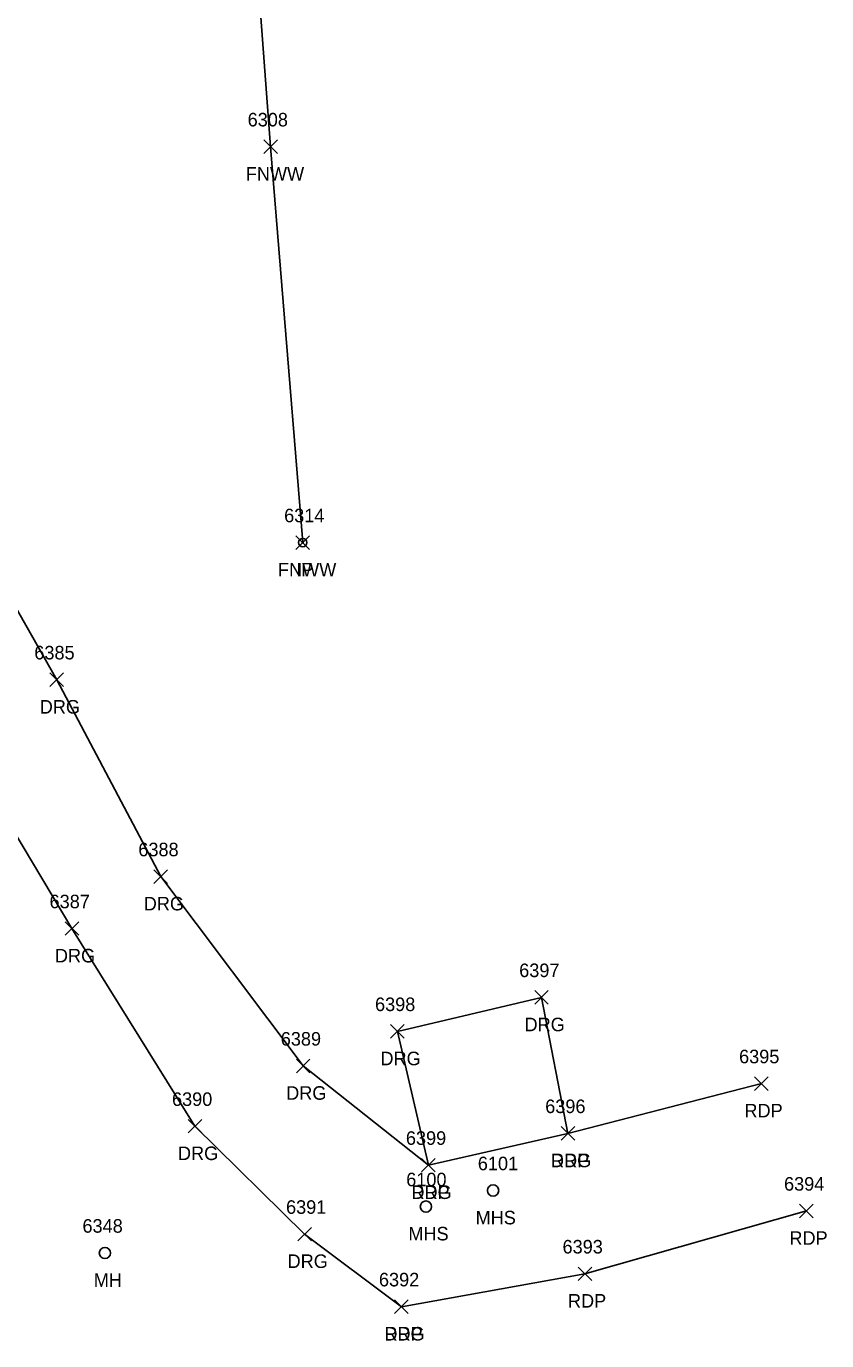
# Model space of a CAD drawing. Extents: x 1462668 to 1465147, y 550359 to 557351.
# Drawn here: x 1465029 to 1465147.2, y 551060.4 to 551254.6 of the extents above; entities that cross this region are included whole.
import ezdxf

# ---------------------------------------------------------------- set-up
doc = ezdxf.new("R2010")
doc.units = 0
for name, color, linetype in [('L_A', 7, 'Continuous'), ('L_I', 7, 'Continuous'), ('L_TIC', 7, 'Continuous'), ('LFNC', 7, 'Continuous'), ('M_A', 7, 'Continuous'), ('M_I', 7, 'Continuous'), ('MPIR', 7, 'Continuous'), ('P_A', 7, 'Continuous'), ('P_I', 7, 'Continuous'), ('P_TIC', 7, 'Continuous'), ('PET', 7, 'Continuous'), ('R_A', 7, 'Continuous'), ('R_I', 7, 'Continuous'), ('R_TIC', 7, 'Continuous'), ('RDG', 7, 'Continuous'), ('U_A', 7, 'Continuous'), ('U_I', 7, 'Continuous'), ('USMH', 7, 'Continuous'), ('UUMH', 7, 'Continuous')]:
    doc.layers.add(name, color=color, linetype=linetype)

msp = doc.modelspace()

# ---------------------------------------------------------------- linework, layer by layer
at = {"layer": 'L_TIC'}
for points in [[(1465064.12, 551235.79), (1465066.12, 551237.79)], [(1465066.12, 551235.79), (1465064.12, 551237.79)], [(1465068.86, 551177.31), (1465070.86, 551179.31)], [(1465070.86, 551177.31), (1465068.86, 551179.31)]]:
    msp.add_lwpolyline(points, dxfattribs=at)
at = {"layer": 'LFNC'}
msp.add_lwpolyline([(1465059.52, 551311.49), (1465065.12, 551236.79), (1465069.86, 551178.31)], dxfattribs=at)
at = {"layer": 'MPIR'}
for radius in [0.625, 0.0833]:
    msp.add_circle((1465069.86, 551178.31), radius, dxfattribs=at)
at = {"layer": 'P_TIC'}
for points in [[(1465136.6, 551097.39), (1465138.6, 551099.39)], [(1465138.6, 551097.39), (1465136.6, 551099.39)], [(1465108.03, 551090.03), (1465110.03, 551092.03)], [(1465110.03, 551090.03), (1465108.03, 551092.03)], [(1465087.42, 551085.34), (1465089.42, 551087.34)], [(1465089.42, 551085.34), (1465087.42, 551087.34)], [(1465143.24, 551078.57), (1465145.24, 551080.57)], [(1465145.24, 551078.57), (1465143.24, 551080.57)], [(1465110.54, 551069.29), (1465112.54, 551071.29)], [(1465112.54, 551069.29), (1465110.54, 551071.29)], [(1465083.43, 551064.43), (1465085.43, 551066.43)], [(1465085.43, 551064.43), (1465083.43, 551066.43)]]:
    msp.add_lwpolyline(points, dxfattribs=at)
at = {"layer": 'PET'}
for points in [[(1465137.6, 551098.39), (1465109.03, 551091.03), (1465088.42, 551086.34)], [(1465084.43, 551065.43), (1465111.54, 551070.29), (1465144.24, 551079.57)]]:
    msp.add_lwpolyline(points, dxfattribs=at)
at = {"layer": 'R_TIC'}
for points in [[(1465032.54, 551157.05), (1465034.54, 551159.05)], [(1465034.54, 551157.05), (1465032.54, 551159.05)], [(1465047.9, 551127.97), (1465049.9, 551129.97)], [(1465049.9, 551127.97), (1465047.9, 551129.97)], [(1465034.78, 551120.29), (1465036.78, 551122.29)], [(1465036.78, 551120.29), (1465034.78, 551122.29)], [(1465104.13, 551110.12), (1465106.13, 551112.12)], [(1465106.13, 551110.12), (1465104.13, 551112.12)], [(1465082.85, 551105.1), (1465084.85, 551107.1)], [(1465084.85, 551105.1), (1465082.85, 551107.1)], [(1465068.93, 551100), (1465070.93, 551102)], [(1465070.93, 551100), (1465068.93, 551102)], [(1465052.95, 551091.09), (1465054.95, 551093.09)], [(1465054.95, 551091.09), (1465052.95, 551093.09)], [(1465108.03, 551090.03), (1465110.03, 551092.03)], [(1465110.03, 551090.03), (1465108.03, 551092.03)], [(1465087.42, 551085.34), (1465089.42, 551087.34)], [(1465089.42, 551085.34), (1465087.42, 551087.34)], [(1465087.42, 551085.34), (1465089.42, 551087.34)], [(1465089.42, 551085.34), (1465087.42, 551087.34)], [(1465069.14, 551075.15), (1465071.14, 551077.15)], [(1465071.14, 551075.15), (1465069.14, 551077.15)], [(1465083.43, 551064.43), (1465085.43, 551066.43)], [(1465085.43, 551064.43), (1465083.43, 551066.43)]]:
    msp.add_lwpolyline(points, dxfattribs=at)
at = {"layer": 'RDG'}
for points in [[(1464982.38, 551474.17), (1464986.33, 551432.77), (1464987.13, 551369.98), (1464986.12, 551312.33), (1464985.91, 551263.05), (1464987.34, 551228.97), (1464997.78, 551186.27), (1465019.82, 551147.97), (1465035.78, 551121.29), (1465053.95, 551092.09), (1465070.14, 551076.15), (1465084.43, 551065.43)], [(1465007.87, 551370.7), (1465004.76, 551315.19), (1465002.49, 551302.22), (1465000.95, 551263.36), (1465002.06, 551232.41), (1465010.64, 551198.4), (1465033.54, 551158.05), (1465048.9, 551128.97), (1465069.93, 551101), (1465088.42, 551086.34)], [(1465109.03, 551091.03), (1465105.13, 551111.12), (1465083.85, 551106.1), (1465088.42, 551086.34)]]:
    msp.add_lwpolyline(points, dxfattribs=at)
at = {"layer": 'USMH'}
for p, q in [((1465097.97, 551082.59), (1465097.97, 551082.59)), ((1465098.8, 551082.59), (1465098.8, 551082.59)), ((1465088.05, 551080.22), (1465088.05, 551080.22)), ((1465088.89, 551080.22), (1465088.89, 551080.22))]:
    msp.add_line(p, q, dxfattribs=at)
for centre in [(1465097.97, 551082.59), (1465088.05, 551080.22)]:
    msp.add_circle(centre, 0.833, dxfattribs=at)
at = {"layer": 'UUMH'}
for p, q in [((1465040.65, 551073.36), (1465040.65, 551073.36)), ((1465041.48, 551073.36), (1465041.48, 551073.36))]:
    msp.add_line(p, q, dxfattribs=at)
msp.add_circle((1465040.65, 551073.36), 0.833, dxfattribs=at)

# ---------------------------------------------------------------- texts
at = {"layer": 'L_A'}
for p in [(1465061.46, 551231.79), (1465066.21, 551173.31)]:
    msp.add_text('FNWW', height=2, dxfattribs=at).set_placement(p)
at = {"layer": 'L_I'}
for s, p in [('6308', (1465061.73, 551239.79)), ('6314', (1465067.12, 551181.31))]:
    msp.add_text(s, height=2, dxfattribs=at).set_placement(p)
at = {"layer": 'M_A'}
msp.add_text('IP', height=2, dxfattribs=at).set_placement((1465068.91, 551173.31))
at = {"layer": 'M_I'}
msp.add_text('6314', height=2, dxfattribs=at).set_placement((1465067.12, 551181.31))
at = {"layer": 'P_A'}
for p in [(1465135.09, 551093.39), (1465106.52, 551086.03), (1465085.91, 551081.34), (1465141.73, 551074.57), (1465109.03, 551065.29), (1465081.92, 551060.43)]:
    msp.add_text('RDP', height=2, dxfattribs=at).set_placement(p)
at = {"layer": 'P_I'}
for s, p in [('6395', (1465134.3, 551101.39)), ('6396', (1465105.67, 551094.03)), ('6399', (1465085.1, 551089.34)), ('6394', (1465140.94, 551082.57)), ('6393', (1465108.23, 551073.29)), ('6392', (1465081.12, 551068.43))]:
    msp.add_text(s, height=2, dxfattribs=at).set_placement(p)
at = {"layer": 'R_A'}
for p in [(1465031.03, 551153.05), (1465046.39, 551123.97), (1465033.27, 551116.29), (1465102.62, 551106.12), (1465081.34, 551101.1), (1465067.42, 551096), (1465051.44, 551087.09), (1465106.52, 551086.03), (1465085.91, 551081.34), (1465085.91, 551081.34), (1465067.63, 551071.15), (1465081.92, 551060.43)]:
    msp.add_text('DRG', height=2, dxfattribs=at).set_placement(p)
at = {"layer": 'R_I'}
for s, p in [('6385', (1465030.23, 551161.05)), ('6388', (1465045.59, 551131.97)), ('6387', (1465032.48, 551124.29)), ('6397', (1465101.83, 551114.12)), ('6398', (1465080.54, 551109.1)), ('6389', (1465066.62, 551104)), ('6390', (1465050.56, 551095.09)), ('6396', (1465105.67, 551094.03)), ('6399', (1465085.1, 551089.34)), ('6399', (1465085.1, 551089.34)), ('6391', (1465067.4, 551079.15)), ('6392', (1465081.12, 551068.43))]:
    msp.add_text(s, height=2, dxfattribs=at).set_placement(p)
at = {"layer": 'U_A'}
for s, p in [('MHS', (1465095.39, 551077.59)), ('MHS', (1465085.47, 551075.22)), ('MH', (1465039.01, 551068.36))]:
    msp.add_text(s, height=2, dxfattribs=at).set_placement(p)
at = {"layer": 'U_I'}
for s, p in [('6101', (1465095.72, 551085.59)), ('6100', (1465085.15, 551083.22)), ('6348', (1465037.34, 551076.36))]:
    msp.add_text(s, height=2, dxfattribs=at).set_placement(p)

doc.saveas('drawing.dxf')
